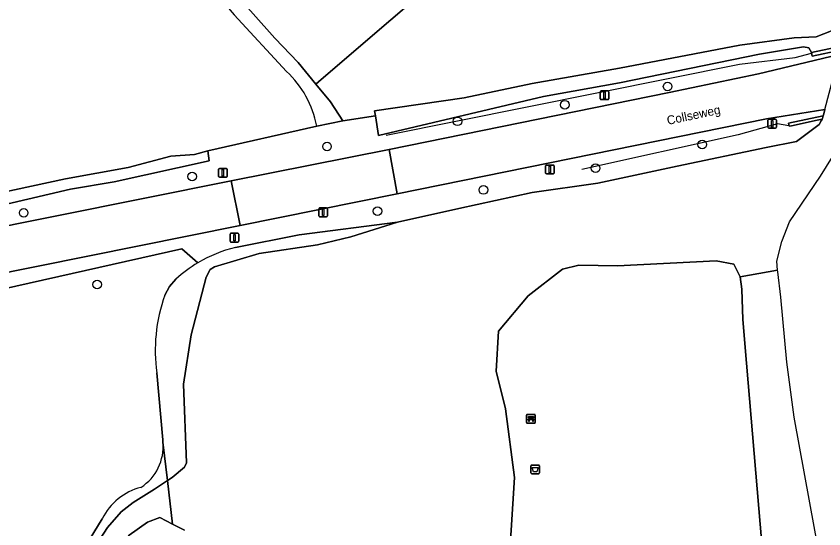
# Model space of a CAD drawing. Extents: x 164494 to 166241, y 382475 to 384495.
# Drawn here: x 165431.6 to 165523.2, y 384056.4 to 384114.4 of the extents above; entities that cross this region are included whole.
import ezdxf

# ---------------------------------------------------------------- set-up
doc = ezdxf.new("R2010")
doc.units = 0
for name, color, linetype in [('IMGEO_Afsluitpaal', 7, 'Continuous'), ('IMGEO_Afvalbak', 7, 'Continuous'), ('IMGEO_Bank', 7, 'Continuous'), ('IMGEO_Boom', 7, 'Continuous'), ('IMGEO_Erf', 7, 'Continuous'), ('IMGEO_Grasland_agrarisch', 7, 'Continuous'), ('IMGEO_Groenvoorziening', 7, 'Continuous'), ('IMGEO_Hek', 7, 'Continuous'), ('IMGEO_Lichtmast', 7, 'Continuous'), ('IMGEO_Loofbos', 7, 'Continuous'), ('IMGEO_Muur', 7, 'Continuous'), ('IMGEO_Oever', 7, 'Continuous'), ('IMGEO_Openbare_ruimte_label', 7, 'Continuous'), ('IMGEO_Rijbaan_lokaal_gesloten', 7, 'Continuous'), ('IMGEO_Rivier', 7, 'Continuous'), ('IMGEO_Verkeersbordpaal', 7, 'Continuous'), ('IMGEO_Waterloop', 7, 'Continuous')]:
    doc.layers.add(name, color=color, linetype=linetype)

msp = doc.modelspace()

# ---------------------------------------------------------------- linework, layer by layer
at = {"layer": 'IMGEO_Afsluitpaal'}
for p, q in [((165497.798, 384105.088), (165497.798, 384105.888)), ((165497.798, 384105.888), (165497.798, 384105.088)), ((165497.898, 384105.988), (165498.688, 384105.988)), ((165498.688, 384105.988), (165497.898, 384105.988)), ((165498.788, 384105.888), (165498.788, 384105.088)), ((165498.788, 384105.088), (165498.788, 384105.888)), ((165498.688, 384104.988), (165497.898, 384104.988)), ((165497.898, 384104.988), (165498.688, 384104.988))]:
    msp.add_line(p, q, dxfattribs=at)
msp.add_lwpolyline([(165498.218, 384105.863), (165498.368, 384105.863), (165498.368, 384105.113), (165498.218, 384105.113), (165498.218, 384105.863)], dxfattribs=at)
for centre, start, end in [((165497.898, 384105.888), 90, 180), ((165497.898, 384105.888), 90, 180), ((165498.688, 384105.888), 0, 90), ((165498.688, 384105.888), 360, 90), ((165497.898, 384105.088), 180, 270), ((165497.898, 384105.088), 180, 270), ((165498.688, 384105.088), 270, 0), ((165498.688, 384105.088), 270, 0)]:
    msp.add_arc(centre, 0.1, start, end, dxfattribs=at)
at = {"layer": 'IMGEO_Afvalbak'}
for p, q in [((165489.943, 384062.683), (165489.943, 384063.483)), ((165489.943, 384063.483), (165489.943, 384062.683)), ((165490.043, 384063.583), (165490.833, 384063.583)), ((165490.833, 384063.583), (165490.043, 384063.583)), ((165490.933, 384063.483), (165490.933, 384062.683)), ((165490.933, 384062.683), (165490.933, 384063.483)), ((165490.833, 384062.583), (165490.043, 384062.583)), ((165490.043, 384062.583), (165490.833, 384062.583))]:
    msp.add_line(p, q, dxfattribs=at)
msp.add_lwpolyline([(165490.086, 384063.297), (165490.79, 384063.297), (165490.641, 384062.827), (165490.235, 384062.827), (165490.086, 384063.297)], dxfattribs=at)
for centre, start, end in [((165490.043, 384063.483), 90, 180), ((165490.043, 384063.483), 90, 180), ((165490.833, 384063.483), 0, 90), ((165490.833, 384063.483), 360, 90), ((165490.043, 384062.683), 180, 270), ((165490.043, 384062.683), 180, 270), ((165490.833, 384062.683), 270, 0), ((165490.833, 384062.683), 270, 0)]:
    msp.add_arc(centre, 0.1, start, end, dxfattribs=at)
at = {"layer": 'IMGEO_Bank'}
for p, q in [((165489.452, 384068.395), (165489.452, 384069.236)), ((165489.452, 384069.236), (165489.452, 384068.395)), ((165489.527, 384069.32), (165490.368, 384069.32)), ((165490.368, 384069.32), (165489.527, 384069.32)), ((165489.761, 384068.826), (165489.761, 384068.932)), ((165489.805, 384068.932), (165489.805, 384068.826)), ((165490.093, 384068.938), (165489.811, 384068.938)), ((165490.099, 384068.826), (165490.099, 384068.932)), ((165490.143, 384068.932), (165490.143, 384068.826)), ((165490.452, 384069.245), (165490.452, 384068.404)), ((165490.452, 384068.404), (165490.452, 384069.245)), ((165490.377, 384068.32), (165489.536, 384068.32)), ((165489.536, 384068.32), (165490.377, 384068.32)), ((165490.149, 384068.718), (165489.756, 384068.718)), ((165489.811, 384068.82), (165490.093, 384068.82))]:
    msp.add_line(p, q, dxfattribs=at)
for points in [[(165489.755, 384068.938), (165489.669, 384068.938), (165489.669, 384069.099), (165490.232, 384069.099), (165490.232, 384068.938), (165490.149, 384068.938)], [(165489.699, 384068.718), (165489.557, 384068.718), (165489.669, 384068.82), (165489.755, 384068.82)], [(165489.749, 384068.711), (165489.749, 384068.504), (165489.706, 384068.504), (165489.706, 384068.711)], [(165490.149, 384068.82), (165490.232, 384068.82), (165490.344, 384068.718), (165490.205, 384068.718)], [(165490.199, 384068.711), (165490.199, 384068.504), (165490.155, 384068.504), (165490.155, 384068.711)]]:
    msp.add_lwpolyline(points, dxfattribs=at)
for centre, radius, start, end in [((165489.53, 384069.242), 0.0779, 92.4484, 184.28452), ((165489.53, 384069.242), 0.0779, 92.4484, 184.28452), ((165489.754, 384068.931), 0.00671, 2.89567, 87.10433), ((165489.811, 384068.931), 0.00671, 92.89567, 177.10433), ((165490.093, 384068.931), 0.00671, 2.89567, 87.10433), ((165490.15, 384068.931), 0.00671, 92.89567, 177.10433), ((165490.374, 384069.242), 0.0779, 2.4484, 94.28452), ((165490.374, 384069.242), 0.0779, 2.4484, 94.28452), ((165489.53, 384068.398), 0.0779, 182.4484, 274.28452), ((165489.53, 384068.398), 0.0779, 182.4484, 274.28452), ((165489.699, 384068.711), 0.00671, 2.89567, 87.10433), ((165489.756, 384068.711), 0.00671, 92.89567, 177.10433), ((165489.754, 384068.827), 0.00671, 272.89567, 357.10433), ((165489.811, 384068.827), 0.00671, 182.89567, 267.10433), ((165490.093, 384068.827), 0.00671, 272.89567, 357.10433), ((165490.15, 384068.827), 0.00671, 182.89567, 267.10433), ((165490.148, 384068.711), 0.00671, 2.89567, 87.10433), ((165490.205, 384068.711), 0.00671, 92.89567, 177.10433), ((165490.374, 384068.398), 0.0779, 272.4484, 4.28452), ((165490.374, 384068.398), 0.0779, 272.4484, 4.28452)]:
    msp.add_arc(centre, radius, start, end, dxfattribs=at)
at = {"layer": 'IMGEO_Boom'}
for centre in [(165505.453, 384106.473), (165493.798, 384104.416), (165481.626, 384102.531), (165466.835, 384099.669), (165509.38, 384099.914), (165497.288, 384097.219), (165451.549, 384096.274), (165484.561, 384094.754), (165472.545, 384092.339), (165432.445, 384092.16), (165440.766, 384084.039)]:
    msp.add_circle(centre, 0.489, dxfattribs=at)
at = {"layer": 'IMGEO_Erf'}
for points in [[(165452.198, 384086.5), (165450.367, 384088.075), (165420.581, 384081.409), (165419.584, 384082.942), (165415.596, 384080.216), (165421.157, 384072.086), (165417.913, 384069.799), (165420.915, 384066.582), (165414.624, 384060.384), (165410.357, 384064.715), (165408.991, 384063.791), (165403.577, 384071.996), (165413.421, 384078.728), (165412.998, 384079.325), (165412.511, 384080.132), (165404.074, 384074.333), (165403.548, 384075.178), (165393.462, 384068.193), (165394.614, 384066.341)], [(165448.457, 384082.827), (165448.986, 384083.805), (165449.693, 384084.664)], [(165448.235, 384066.177), (165448.202, 384066.455), (165447.549, 384074.05)], [(165409.157, 384052.399), (165413.571, 384049.73), (165419.448, 384047.004), (165432.21, 384040.827), (165432.889, 384042.04), (165432.059, 384042.703), (165431.835, 384043.241), (165432.508, 384044.106), (165433.832, 384046.315), (165434.934, 384048.823), (165437.077, 384050.998), (165439.037, 384053.712), (165441.349, 384057.507)]]:
    msp.add_lwpolyline(points, dxfattribs=at)
for centre, radius, start, end in [((165460.363, 384072.733), 16.006, 120.67156, 131.80637), ((165464.091, 384076.956), 16.7, 159.419, 175.10618), ((165464.238, 384076.59), 16.881, 173.91085, 188.65519), ((165442.76, 384065.678), 5.498, 302.8365, 5.21239), ((165447.455, 384054.447), 6.83, 104.53173, 153.38042)]:
    msp.add_arc(centre, radius, start, end, dxfattribs=at)
at = {"layer": 'IMGEO_Grasland_agrarisch'}
msp.add_lwpolyline([(165490.146, 384127.829), (165466.166, 384107.255), (165465.569, 384106.743), (165467.222, 384104.728), (165468.636, 384102.579), (165472.346, 384103.149), (165472.223, 384103.729), (165482.38, 384105.191), (165490.094, 384106.83), (165500, 384108.557), (165513.65, 384111.177), (165519.801, 384112), (165522.28, 384112.098), (165525.965, 384113.544), (165527.032, 384116.873)], dxfattribs=at)
at = {"layer": 'IMGEO_Groenvoorziening'}
for points in [[(165455.716, 384117.846), (165460.935, 384111.944), (165463.552, 384109.202), (165465.569, 384106.743), (165466.166, 384107.255), (165490.146, 384127.829)], [(165416.203, 384087.817), (165455.965, 384095.8), (165473.875, 384099.349), (165505.633, 384105.792), (165515.757, 384107.925), (165524.914, 384110.113), (165525.035, 384110.579), (165521.835, 384109.915), (165521.755, 384110.335), (165521.469, 384110.852), (165520.848, 384110.968), (165515.857, 384110.153), (165500, 384106.893), (165491.384, 384105.36), (165472.667, 384100.925), (165472.346, 384103.149), (165468.636, 384102.579), (165465.666, 384101.993), (165453.309, 384099.19), (165453.393, 384098.62), (165453.477, 384098.051), (165442.7, 384095.675), (165437.748, 384094.84), (165417.214, 384090.034)], [(165497.556, 384095.525), (165506.541, 384097.437), (165516.619, 384099.573), (165520.078, 384100.258), (165522.619, 384102.163), (165522.854, 384102.571), (165522.974, 384102.779), (165522.403, 384102.657), (165519.48, 384102.032), (165519.212, 384101.976), (165519.156, 384102.326), (165523.094, 384103.146), (165523.158, 384103.389), (165523.28, 384103.856), (165516.675, 384102.818), (165474.797, 384094.323), (165456.979, 384090.714), (165416.608, 384082.604)], [(165456.444, 384088.252), (165463.67, 384089.663), (165474.832, 384091.124), (165481.782, 384092.639), (165490.085, 384094.457), (165497.556, 384095.525)], [(165394.614, 384066.341), (165393.462, 384068.193), (165403.548, 384075.178), (165404.074, 384074.333), (165412.511, 384080.132), (165412.998, 384079.325), (165413.421, 384078.728), (165415.596, 384080.216), (165419.584, 384082.942), (165420.581, 384081.409), (165450.367, 384088.075), (165452.198, 384086.5)], [(165450.666, 384056.192), (165449.323, 384056.885), (165447.886, 384057.626), (165446.488, 384057.105), (165444.409, 384055.62)]]:
    msp.add_lwpolyline(points, dxfattribs=at)
msp.add_arc((165460.369, 384072.719), 16.021, 104.18058, 120.66383, dxfattribs=at)
at = {"layer": 'IMGEO_Hek'}
for points in [[(165473.558, 384100.974), (165513.589, 384108.996), (165519.923, 384109.763), (165521.77, 384110.257)], [(165519.202, 384102.037), (165517.899, 384102.245), (165513.436, 384100.987), (165495.706, 384097.087)]]:
    msp.add_lwpolyline(points, dxfattribs=at)
at = {"layer": 'IMGEO_Lichtmast'}
for p, q in [((165516.808, 384101.861), (165516.808, 384102.661)), ((165516.808, 384102.661), (165516.808, 384101.861)), ((165516.908, 384102.761), (165517.698, 384102.761)), ((165517.698, 384102.761), (165516.908, 384102.761)), ((165517.798, 384102.661), (165517.798, 384101.861)), ((165517.798, 384101.861), (165517.798, 384102.661)), ((165517.698, 384101.761), (165516.908, 384101.761)), ((165516.908, 384101.761), (165517.698, 384101.761)), ((165491.604, 384096.676), (165491.604, 384097.476)), ((165491.604, 384097.476), (165491.604, 384096.676)), ((165491.704, 384097.576), (165492.494, 384097.576)), ((165492.494, 384097.576), (165491.704, 384097.576)), ((165492.594, 384097.476), (165492.594, 384096.676)), ((165492.594, 384096.676), (165492.594, 384097.476)), ((165492.494, 384096.576), (165491.704, 384096.576)), ((165491.704, 384096.576), (165492.494, 384096.576)), ((165465.9, 384091.823), (165465.9, 384092.623)), ((165465.9, 384092.623), (165465.9, 384091.823)), ((165466, 384092.723), (165466.79, 384092.723)), ((165466.79, 384092.723), (165466, 384092.723)), ((165466.89, 384092.623), (165466.89, 384091.823)), ((165466.89, 384091.823), (165466.89, 384092.623)), ((165466.79, 384091.723), (165466, 384091.723)), ((165466, 384091.723), (165466.79, 384091.723))]:
    msp.add_line(p, q, dxfattribs=at)
for points in [[(165517.228, 384102.636), (165517.378, 384102.636), (165517.378, 384101.886), (165517.228, 384101.886), (165517.228, 384102.636)], [(165492.024, 384097.451), (165492.174, 384097.451), (165492.174, 384096.701), (165492.024, 384096.701), (165492.024, 384097.451)], [(165466.32, 384092.598), (165466.47, 384092.598), (165466.47, 384091.848), (165466.32, 384091.848), (165466.32, 384092.598)]]:
    msp.add_lwpolyline(points, dxfattribs=at)
for centre, start, end in [((165516.908, 384102.661), 90, 180), ((165516.908, 384102.661), 90, 180), ((165517.698, 384102.661), 0, 90), ((165517.698, 384102.661), 360, 90), ((165516.908, 384101.861), 180, 270), ((165516.908, 384101.861), 180, 270), ((165517.698, 384101.861), 270, 0), ((165517.698, 384101.861), 270, 0), ((165491.704, 384097.476), 90, 180), ((165491.704, 384097.476), 90, 180), ((165492.494, 384097.476), 0, 90), ((165492.494, 384097.476), 360, 90), ((165491.704, 384096.676), 180, 270), ((165491.704, 384096.676), 180, 270), ((165492.494, 384096.676), 270, 0), ((165492.494, 384096.676), 270, 0), ((165466, 384092.623), 90, 180), ((165466, 384092.623), 90, 180), ((165466, 384091.823), 180, 270), ((165466, 384091.823), 180, 270), ((165466.79, 384092.623), 0, 90), ((165466.79, 384092.623), 360, 90), ((165466.79, 384091.823), 270, 0), ((165466.79, 384091.823), 270, 0)]:
    msp.add_arc(centre, 0.1, start, end, dxfattribs=at)
at = {"layer": 'IMGEO_Loofbos'}
for points in [[(165376.045, 384120.378), (165393.36, 384102.543), (165396.427, 384098.959), (165399.604, 384095.649), (165400.755, 384094.137), (165402.204, 384092.608), (165404.135, 384090.901), (165406.542, 384089.799), (165407.082, 384089.702), (165409.719, 384089.801), (165415.947, 384091.045), (165419.918, 384091.993), (165421.732, 384092.686), (165437.2, 384096.016), (165444.307, 384097.307), (165449.115, 384098.581), (165451.793, 384098.76), (165453.309, 384099.19), (165465.666, 384101.993)], [(165462.24, 384108.193), (165456.299, 384114.591)], [(165517.326, 384040.425), (165514.398, 384075.127), (165513.99, 384080.078), (165513.847, 384083.517), (165513.672, 384084.918), (165512.959, 384086.354), (165510.964, 384086.706), (165499.755, 384086.146), (165495.373, 384086.224), (165493.518, 384085.762), (165489.655, 384082.749), (165486.295, 384078.745), (165486.005, 384074.226), (165487.053, 384069.945), (165488.101, 384062.158), (165487.517, 384053.227)]]:
    msp.add_lwpolyline(points, dxfattribs=at)
msp.add_arc((165454.575, 384099.911), 11.284, 10.63153, 47.21685, dxfattribs=at)
at = {"layer": 'IMGEO_Muur'}
for points in [[(165521.755, 384110.335), (165521.835, 384109.915), (165525.035, 384110.579), (165525.125, 384110.923), (165525.16, 384111.031)], [(165519.156, 384102.326), (165519.212, 384101.976), (165519.48, 384102.032), (165522.403, 384102.657), (165522.974, 384102.779), (165523.019, 384102.858), (165523.094, 384103.146)]]:
    msp.add_lwpolyline(points, close=True, dxfattribs=at)
at = {"layer": 'IMGEO_Oever'}
for points in [[(165448.235, 384066.177), (165448.745, 384061.816), (165449.276, 384062.168), (165450.663, 384063.34), (165450.889, 384063.841), (165450.567, 384072.755), (165451.414, 384078.332), (165453.127, 384084.887), (165453.574, 384085.732), (165454.067, 384086.047), (165459.144, 384087.566), (165465.747, 384088.541), (165469.52, 384089.435), (165474.832, 384091.124), (165463.67, 384089.663), (165456.444, 384088.252)], [(165449.693, 384084.664), (165448.986, 384083.805), (165448.457, 384082.827)], [(165447.549, 384074.05), (165448.202, 384066.455), (165448.235, 384066.177)], [(165448.745, 384061.816), (165448.235, 384066.177)], [(165441.349, 384057.507), (165439.037, 384053.712), (165437.077, 384050.998), (165434.934, 384048.823), (165433.832, 384046.315), (165432.508, 384044.106), (165431.835, 384043.241), (165432.059, 384042.703), (165432.889, 384042.04), (165433.161, 384041.976), (165432.759, 384042.615), (165435.98, 384047.93), (165438.654, 384051.429), (165441.935, 384056.511), (165443.481, 384058.289), (165444.876, 384059.343), (165447.278, 384060.842), (165448.745, 384061.816)]]:
    msp.add_lwpolyline(points, dxfattribs=at)
for centre, radius, start, end in [((165460.369, 384072.719), 16.021, 104.18058, 120.66383), ((165460.363, 384072.733), 16.006, 120.67156, 131.80637), ((165464.091, 384076.956), 16.7, 159.419, 175.10618), ((165464.238, 384076.59), 16.881, 173.91085, 188.65519), ((165442.76, 384065.678), 5.498, 302.8365, 5.21239), ((165447.455, 384054.447), 6.83, 104.53173, 153.38042)]:
    msp.add_arc(centre, radius, start, end, dxfattribs=at)
at = {"layer": 'IMGEO_Rijbaan_lokaal_gesloten'}
for points in [[(165516.675, 384102.818), (165523.28, 384103.856), (165524.25, 384107.573), (165524.914, 384110.113), (165515.757, 384107.925), (165505.633, 384105.792), (165473.875, 384099.349), (165474.797, 384094.323)], [(165473.875, 384099.349), (165455.965, 384095.8), (165456.979, 384090.714), (165474.797, 384094.323)]]:
    msp.add_lwpolyline(points, close=True, dxfattribs=at)
for points in [[(165456.979, 384090.714), (165455.965, 384095.8), (165416.203, 384087.817), (165411.913, 384087.024)], [(165416.608, 384082.604), (165456.979, 384090.714)]]:
    msp.add_lwpolyline(points, dxfattribs=at)
at = {"layer": 'IMGEO_Rivier'}
for points in [[(165523.28, 384103.856), (165523.158, 384103.389), (165523.094, 384103.146), (165523.019, 384102.858), (165522.974, 384102.779), (165522.854, 384102.571), (165522.619, 384102.163), (165520.078, 384100.258), (165516.619, 384099.573), (165506.541, 384097.437), (165497.556, 384095.525), (165490.085, 384094.457), (165481.782, 384092.639), (165474.832, 384091.124), (165469.52, 384089.435), (165465.747, 384088.541), (165459.144, 384087.566), (165454.067, 384086.047), (165453.574, 384085.732), (165453.127, 384084.887), (165451.414, 384078.332), (165450.567, 384072.755), (165450.889, 384063.841), (165450.663, 384063.34), (165449.276, 384062.168), (165448.745, 384061.816), (165449.323, 384056.885), (165450.666, 384056.192)], [(165487.517, 384053.227), (165488.101, 384062.158), (165487.053, 384069.945), (165486.005, 384074.226), (165486.295, 384078.745), (165489.655, 384082.749), (165493.518, 384085.762), (165495.373, 384086.224), (165499.755, 384086.146), (165510.964, 384086.706), (165512.959, 384086.354), (165513.672, 384084.918), (165517.918, 384085.675), (165517.824, 384086.673), (165518.414, 384088.896), (165519.253, 384091.162), (165522.789, 384096.328), (165525.709, 384100.998)], [(165523.269, 384050.023), (165519.785, 384068.995), (165518.981, 384075.228), (165518.268, 384082.62), (165517.936, 384085.479), (165517.918, 384085.675), (165513.672, 384084.918), (165513.847, 384083.517), (165513.99, 384080.078), (165514.398, 384075.127), (165517.326, 384040.425), (165517.882, 384032.878), (165518.715, 384030.641), (165528.619, 384031.237)]]:
    msp.add_lwpolyline(points, dxfattribs=at)
at = {"layer": 'IMGEO_Verkeersbordpaal'}
for p, q in [((165454.539, 384096.296), (165454.539, 384097.096)), ((165454.539, 384097.096), (165454.539, 384096.296)), ((165454.639, 384097.196), (165455.429, 384097.196)), ((165455.429, 384097.196), (165454.639, 384097.196)), ((165455.529, 384097.096), (165455.529, 384096.296)), ((165455.529, 384096.296), (165455.529, 384097.096)), ((165455.429, 384096.196), (165454.639, 384096.196)), ((165454.639, 384096.196), (165455.429, 384096.196)), ((165455.841, 384088.947), (165455.841, 384089.747)), ((165455.841, 384089.747), (165455.841, 384088.947)), ((165455.941, 384089.847), (165456.731, 384089.847)), ((165456.731, 384089.847), (165455.941, 384089.847)), ((165456.831, 384089.747), (165456.831, 384088.947)), ((165456.831, 384088.947), (165456.831, 384089.747)), ((165456.731, 384088.847), (165455.941, 384088.847)), ((165455.941, 384088.847), (165456.731, 384088.847))]:
    msp.add_line(p, q, dxfattribs=at)
for points in [[(165454.959, 384097.071), (165455.109, 384097.071), (165455.109, 384096.321), (165454.959, 384096.321), (165454.959, 384097.071)], [(165456.261, 384089.722), (165456.411, 384089.722), (165456.411, 384088.972), (165456.261, 384088.972), (165456.261, 384089.722)]]:
    msp.add_lwpolyline(points, dxfattribs=at)
for centre, start, end in [((165454.639, 384097.096), 90, 180), ((165454.639, 384097.096), 90, 180), ((165455.429, 384097.096), 0, 90), ((165455.429, 384097.096), 360, 90), ((165454.639, 384096.296), 180, 270), ((165454.639, 384096.296), 180, 270), ((165455.429, 384096.296), 270, 0), ((165455.429, 384096.296), 270, 0), ((165455.941, 384089.747), 90, 180), ((165455.941, 384089.747), 90, 180), ((165456.731, 384089.747), 0, 90), ((165456.731, 384089.747), 360, 90), ((165455.941, 384088.947), 180, 270), ((165455.941, 384088.947), 180, 270), ((165456.731, 384088.947), 270, 0), ((165456.731, 384088.947), 270, 0)]:
    msp.add_arc(centre, 0.1, start, end, dxfattribs=at)
at = {"layer": 'IMGEO_Waterloop'}
for points in [[(165396.427, 384098.959), (165393.36, 384102.543), (165376.045, 384120.378), (165371.059, 384125.95), (165369.983, 384127.153), (165369.194, 384128.508), (165368.786, 384129.525), (165371.845, 384132.306), (165379.838, 384138.363), (165397.437, 384150.983), (165410.628, 384160.2), (165419.903, 384165.794), (165426.11, 384155.983), (165431.819, 384145.094), (165434.692, 384140.895), (165436.544, 384138.189), (165443.618, 384129.92), (165449.748, 384122.324), (165456.299, 384114.591), (165462.24, 384108.193)], [(165465.666, 384101.993), (165468.636, 384102.579), (165467.222, 384104.728), (165465.569, 384106.743), (165463.552, 384109.202), (165460.935, 384111.944), (165455.716, 384117.846), (165453.455, 384121.09), (165450.474, 384124.249), (165445.569, 384131.034), (165444.86, 384132.449)], [(165417.214, 384090.034), (165437.748, 384094.84), (165442.7, 384095.675), (165453.477, 384098.051), (165453.393, 384098.62), (165453.309, 384099.19), (165451.793, 384098.76), (165449.115, 384098.581), (165444.307, 384097.307), (165437.2, 384096.016), (165421.732, 384092.686)]]:
    msp.add_lwpolyline(points, dxfattribs=at)
for points in [[(165515.857, 384110.153), (165520.848, 384110.968), (165521.469, 384110.852), (165521.755, 384110.335), (165525.16, 384111.031), (165525.965, 384113.544), (165522.28, 384112.098), (165519.801, 384112), (165513.65, 384111.177), (165500, 384108.557), (165490.094, 384106.83), (165482.38, 384105.191), (165472.223, 384103.729), (165472.346, 384103.149), (165472.667, 384100.925), (165491.384, 384105.36), (165500, 384106.893)], [(165444.409, 384055.62), (165446.488, 384057.105), (165447.886, 384057.626), (165449.323, 384056.885), (165448.745, 384061.816), (165447.278, 384060.842), (165444.876, 384059.343), (165443.481, 384058.289), (165441.935, 384056.511), (165438.654, 384051.429), (165435.98, 384047.93), (165432.759, 384042.615), (165433.161, 384041.976), (165433.992, 384041.779), (165434.805, 384041.502), (165435.262, 384041.866)]]:
    msp.add_lwpolyline(points, close=True, dxfattribs=at)
msp.add_arc((165454.575, 384099.911), 11.284, 10.63153, 47.21685, dxfattribs=at)

# ---------------------------------------------------------------- texts
at = {"layer": 'IMGEO_Openbare_ruimte_label'}
msp.add_text('Collseweg', height=1, rotation=12.00671, dxfattribs=at).set_placement((165505.479, 384102.12))

doc.saveas('drawing.dxf')
